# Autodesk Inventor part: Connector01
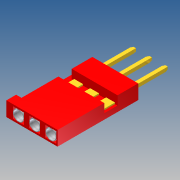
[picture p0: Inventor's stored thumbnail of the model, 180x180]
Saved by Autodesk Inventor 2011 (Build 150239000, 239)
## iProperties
Created: 2008-05
Part Number: Connector01
Document SubType Name: Modeling
Density: 1 g/cm^3
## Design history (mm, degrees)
feature "Base1"
body "Solid1"
